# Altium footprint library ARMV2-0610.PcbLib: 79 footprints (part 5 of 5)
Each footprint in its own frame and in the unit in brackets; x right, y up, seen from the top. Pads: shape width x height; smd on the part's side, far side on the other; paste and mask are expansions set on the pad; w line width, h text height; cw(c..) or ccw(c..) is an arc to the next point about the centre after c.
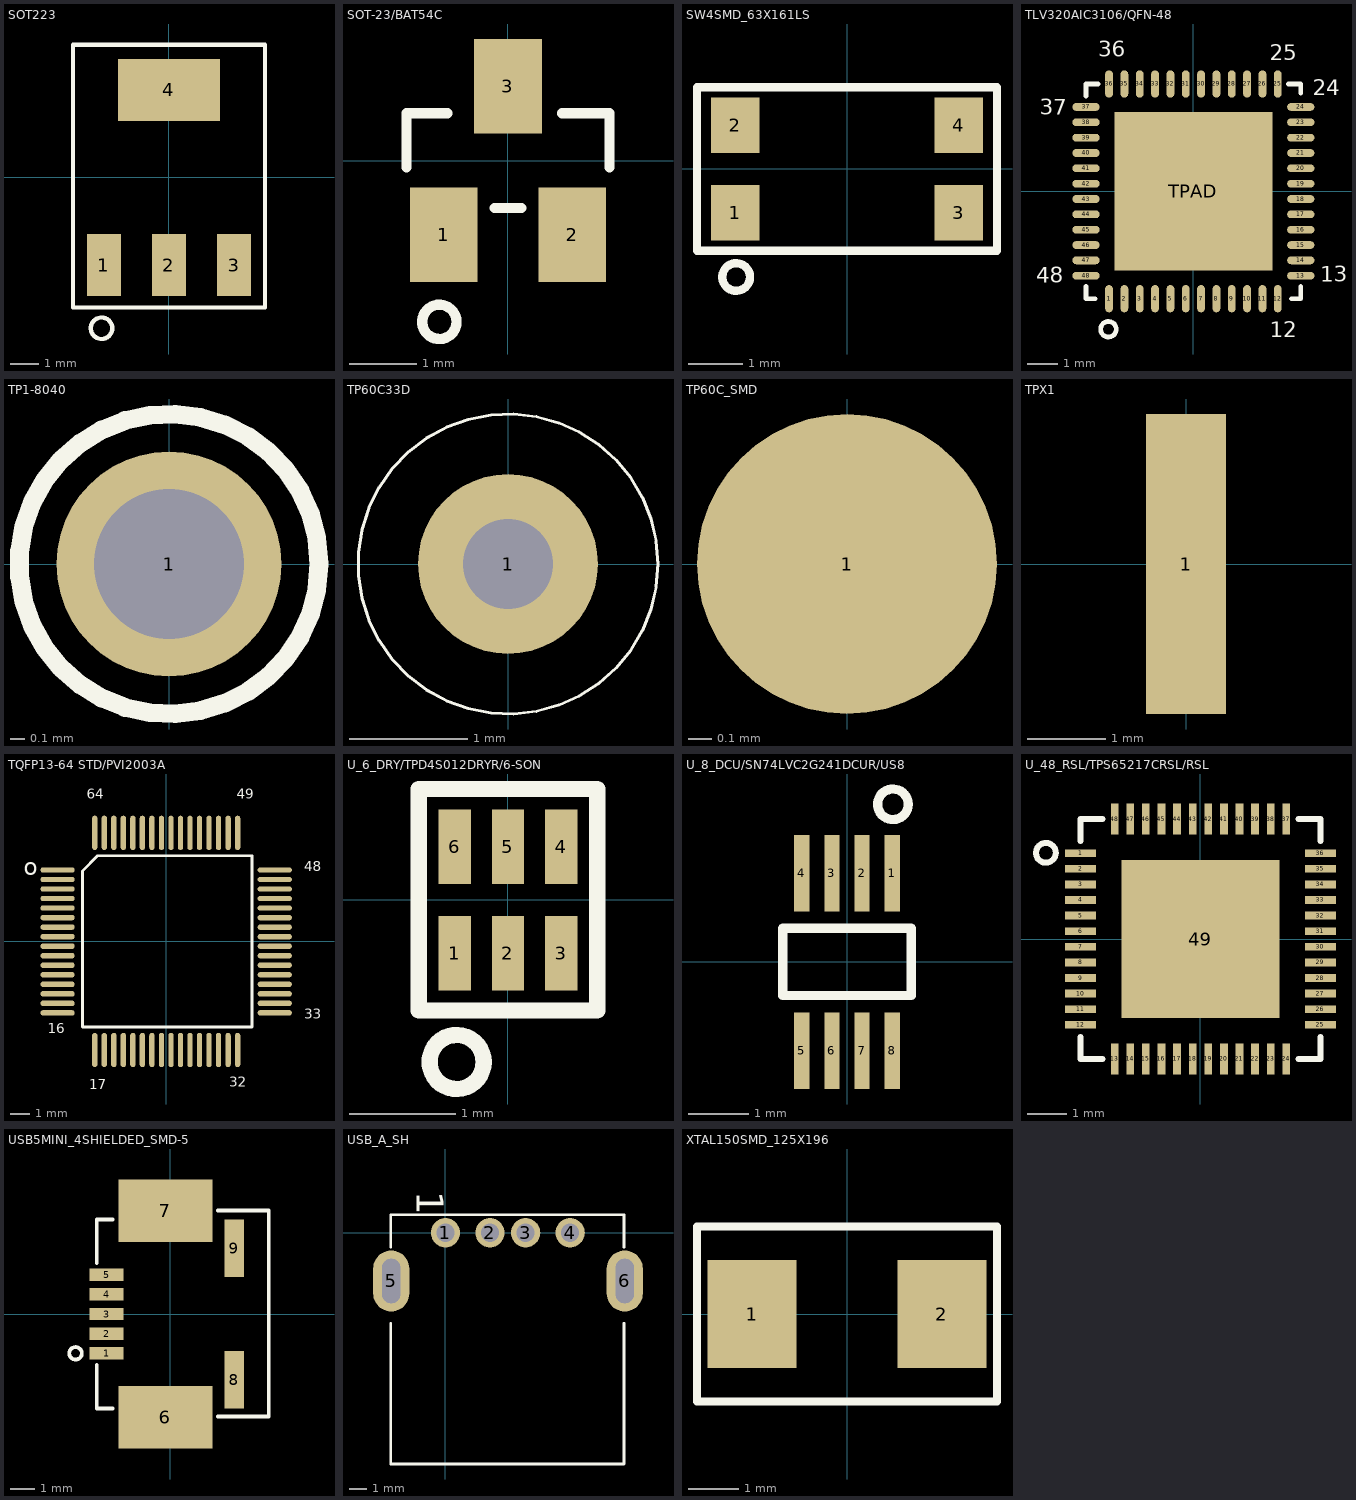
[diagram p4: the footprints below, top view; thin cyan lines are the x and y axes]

## SOT223 [mm]
height 1.8
pads (4):
  rect 1.2x2.2 smd: 1(-2.3,-3.1) 2(0,-3.1) 3(2.3,-3.1)
  rect 3.6x2.2 smd: 4(0,3.1)
Top Overlay:
  circle w0.152: c-2.388,-5.334 r0.381
  lines w0.15: -3.4,-4.6 3.4,-4.6 3.4,4.7 -3.4,4.7 -3.4,-4.6

## SOT-23/BAT54C [mm]
pads (3):
  rect 1x1.4 smd: 1(-0.95,-1.1) 2(0.95,-1.1) 3(0,1.1)
Top Overlay:
  circle w0.152: c-1.016,-2.388 r0.254
  lines w0.15: -1.5,-0.1 -1.5,0.7 -0.9,0.7 ; -0.2,-0.7 0.2,-0.7 ; 0.8,0.7 1.5,0.7 1.5,-0.1

## SW4SMD_63X161LS [mil] "SW4SMD_63X161LS"
pads (4):
  rect 35x40 smd mask+2: 1(-80.71,-31.5) 2(-80.71,31.5) 3(80.71,-31.5) 4(80.71,31.5)
Top Overlay:
  circle w6: c-80,-78 r10
  lines w6: -108.27,-59.06 -108.27,59.06 108.27,59.06 108.27,-59.06 -108.27,-59.06

## TLV320AIC3106/QFN-48 [mil]
height 39.37
pads (49):
  oval 10x35 smd: 1(-108.27,-137.8) 2(-88.58,-137.8) 3(-68.9,-137.8) 4(-49.21,-137.8) 5(-29.53,-137.8) 6(-9.84,-137.8) 7(9.84,-137.8) 8(29.53,-137.8) 9(49.21,-137.8) 10(68.9,-137.8) 11(88.58,-137.8) 12(108.27,-137.8) 25(108.27,137.8) 26(88.58,137.8) 27(68.9,137.8) 28(49.21,137.8) 29(29.53,137.8) 30(9.84,137.8) 31(-9.84,137.8) 32(-29.53,137.8) 33(-49.21,137.8) 34(-68.9,137.8) 35(-88.58,137.8) 36(-108.27,137.8)
  oval 35x10 smd: 13(137.8,-108.27) 14(137.8,-88.58) 15(137.8,-68.9) 16(137.8,-49.21) 17(137.8,-29.53) 18(137.8,-9.84) 19(137.8,9.84) 20(137.8,29.53) 21(137.8,49.21) 22(137.8,68.9) 23(137.8,88.58) 24(137.8,108.27) 37(-137.8,108.27) 38(-137.8,88.58) 39(-137.8,68.9) 40(-137.8,49.21) 41(-137.8,29.53) 42(-137.8,9.84) 43(-137.8,-9.84) 44(-137.8,-29.53) 45(-137.8,-49.21) 46(-137.8,-68.9) 47(-137.8,-88.58) 48(-137.8,-108.27)
  rect 203x203 smd: TPAD(0,0)
Top Overlay:
  circle w6: c-109,-177 r10
  lines w6: -137.8,-122.05 -137.8,-137.8 -125.98,-137.8 ; -137.8,122.05 -137.8,137.8 -122.05,137.8 ; 122.05,137.8 137.8,137.8 137.8,125.98 ; 125.98,-137.8 137.8,-137.8 137.8,-122.05
  text "12" at 98,-187 h20
  text "13" at 163,-116 h20
  text "24" at 153,123 h20
  text "25" at 98,168 h20
  text "36" at -122,173 h20
  text "37" at -197,98 h20
  text "48" at -202,-117 h20

## TP1-8040 [mil] "TP1-8040"
pads (1):
  round 60 hole 40 mask+2: 1(0,0)
Top Overlay:
  circle w5: c0,0 r40

## TP60C33D [mil] "TP60C33D"
pads (1):
  round 60 hole 30 mask+2: 1(0,0)
Top Overlay:
  circle w1: c0,0 r50

## TP60C_SMD [mil] "TP60C_SMD"
pads (1):
  round 50 smd mask+2: 1(0,0)

## TPX1 [mil]
pads (1):
  rect 40x150 smd: 1(0,0)

## TQFP13-64 STD/PVI2003A [mm]
height 1.2
pads (64):
  oval 1.8x0.28 smd: 1(-5.7,3.75) 2(-5.7,3.25) 3(-5.7,2.75) 4(-5.7,2.25) 5(-5.7,1.75) 6(-5.7,1.25) 7(-5.7,0.75) 8(-5.7,0.25) 9(-5.7,-0.25) 10(-5.7,-0.75) 11(-5.7,-1.25) 12(-5.7,-1.75) 13(-5.7,-2.25) 14(-5.7,-2.75) 15(-5.7,-3.25) 16(-5.7,-3.75) 33(5.7,-3.75) 34(5.7,-3.25) 35(5.7,-2.75) 36(5.7,-2.25) 37(5.7,-1.75) 38(5.7,-1.25) 39(5.7,-0.75) 40(5.7,-0.25) 41(5.7,0.25) 42(5.7,0.75) 43(5.7,1.25) 44(5.7,1.75) 45(5.7,2.25) 46(5.7,2.75) 47(5.7,3.25) 48(5.7,3.75)
  oval 0.28x1.8 smd: 17(-3.75,-5.7) 18(-3.25,-5.7) 19(-2.75,-5.7) 20(-2.25,-5.7) 21(-1.75,-5.7) 22(-1.25,-5.7) 23(-0.75,-5.7) 24(-0.25,-5.7) 25(0.25,-5.7) 26(0.75,-5.7) 27(1.25,-5.7) 28(1.75,-5.7) 29(2.25,-5.7) 30(2.75,-5.7) 31(3.25,-5.7) 32(3.75,-5.7) 49(3.75,5.7) 50(3.25,5.7) 51(2.75,5.7) 52(2.25,5.7) 53(1.75,5.7) 54(1.25,5.7) 55(0.75,5.7) 56(0.25,5.7) 57(-0.25,5.7) 58(-0.75,5.7) 59(-1.25,5.7) 60(-1.75,5.7) 61(-2.25,5.7) 62(-2.75,5.7) 63(-3.25,5.7) 64(-3.75,5.7)
Top Overlay:
  lines w0.15: -4.4,-4.5 4.5,-4.5 4.5,4.5 -3.6,4.5 -4.4,3.7 -4.4,-4.5
  text "64" at -4.175,7.493 h0.51
  text "49" at 3.699,7.493 h0.51
  text "48" at 7.255,3.683 h0.51
  text "33" at 7.255,-4.064 h0.51
  text "32" at 3.318,-7.62 h0.51
  text "17" at -4.048,-7.747 h0.51
  text "16" at -6.207,-4.826 h0.51
  text "o" at -7.468,3.48 h0.89

## U_6_DRY/TPD4S012DRYR/6-SON [mm]
pads (6):
  rect 0.305x0.7 smd mask+0.051: 1(-0.5,-0.5) 2(0,-0.5) 3(0.5,-0.5) 4(0.5,0.5) 5(0,0.5) 6(-0.5,0.5)
Top Overlay:
  circle w0.152: c-0.483,-1.524 r0.254
  lines w0.152: -0.838,-1.041 -0.838,1.041 0.838,1.041 0.838,-1.041 -0.838,-1.041

## U_8_DCU/SN74LVC2G241DCUR/US8 [mil]
height 35.43
pads (8):
  rect 10x50 smd mask+2: 1(29.53,58) 2(9.84,58) 3(-9.84,58) 4(-29.53,58) 5(-29.53,-58) 6(-9.84,-58) 7(9.84,-58) 8(29.53,-58)
Top Overlay:
  circle w6: c30,103 r10
  lines w6: -42,-22 42,-22 42,22 -42,22 -42,-22

## U_48_RSL/TPS65217CRSL/RSL [mil]
height 39.37
pads (49):
  rect 31.5x7.87 smd mask+2: 1(-121.06,86.61) 2(-121.06,70.87) 3(-121.06,55.12) 4(-121.06,39.37) 5(-121.06,23.62) 6(-121.06,7.87) 7(-121.06,-7.87) 8(-121.06,-23.62) 9(-121.06,-39.37) 10(-121.06,-55.12) 11(-121.06,-70.87) 12(-121.06,-86.61) 25(121.06,-86.61) 26(121.06,-70.87) 27(121.06,-55.12) 28(121.06,-39.37) 29(121.06,-23.62) 30(121.06,-7.87) 31(121.06,7.87) 32(121.06,23.62) 33(121.06,39.37) 34(121.06,55.12) 35(121.06,70.87) 36(121.06,86.61)
  rect 7.87x31.5 smd mask+2: 13(-86.61,-121.06) 14(-70.87,-121.06) 15(-55.12,-121.06) 16(-39.37,-121.06) 17(-23.62,-121.06) 18(-7.87,-121.06) 19(7.87,-121.06) 20(23.62,-121.06) 21(39.37,-121.06) 22(55.12,-121.06) 23(70.87,-121.06) 24(86.61,-121.06) 37(86.61,121.06) 38(70.87,121.06) 39(55.12,121.06) 40(39.37,121.06) 41(23.62,121.06) 42(7.87,121.06) 43(-7.87,121.06) 44(-23.62,121.06) 45(-39.37,121.06) 46(-55.12,121.06) 47(-70.87,121.06) 48(-86.61,121.06)
  rect 159.45x159.45 smd mask+2: 49(0,0)
Top Overlay:
  circle w6: c-156,87 r10
  lines w6: -121.06,-98.94 -121.06,-121.06 -98.94,-121.06 ; -121.06,98.94 -121.06,121.06 -98.94,121.06 ; 98.94,-121.06 121.06,-121.06 121.06,-98.94 ; 98.94,121.06 121.06,121.06 121.06,98.94

## USB5MINI_4SHIELDED_SMD-5 [mil] "USB5MINI_4SHIELDED_SMD-5"
pads (9):
  rect 55.12x19.69 smd mask+2: 1(-102.36,-62.99) 2(-102.36,-31.5) 3(-102.36,0) 4(-102.36,31.5) 5(-102.36,62.99)
  rect 150x100 smd mask+2: 6(-7.87,-165.35) 7(-7.87,165.35)
  rect 31.5x92.52 smd mask+2: 8(102.36,-105.31) 9(102.36,105.31)
Top Overlay:
  circle w6: c-152,-63 r10
  lines w6: -118.11,-81.14 -118.11,-151.57 -92.68,-151.57 ; -118.11,81.14 -118.11,151.57 -92.68,151.57 ; 75.75,-164.22 157.48,-164.22 157.48,165.78 75.75,165.78

## USB_A_SH [mil]
pads (6):
  round 65 hole 40 mask+2: 1(0,0) 2(98.4,0) 3(177.2,0) 4(275.6,0)
  oval 80x135 hole 40 slot 98.43 at 90 deg mask+2: 5(-120,-106.7) 6(396.5,-106.7)
Top Overlay:
  lines w6: -120.9,-200 -120.9,-511.4 394.9,-511.4 394.9,-200 ; -120.9,-32 -120.9,39.8 394.9,39.8 394.9,-32
  text "1" at -64,92 h60

## XTAL150SMD_125X196 [mil] "XTAL150SMD_125X196"
pads (2):
  rect 70x85 smd mask+2: 1(-74.8,0) 2(74.8,0)
Top Overlay:
  lines w6: -118.11,-68.9 -118.11,68.9 118.11,68.9 118.11,-68.9 -118.11,-68.9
